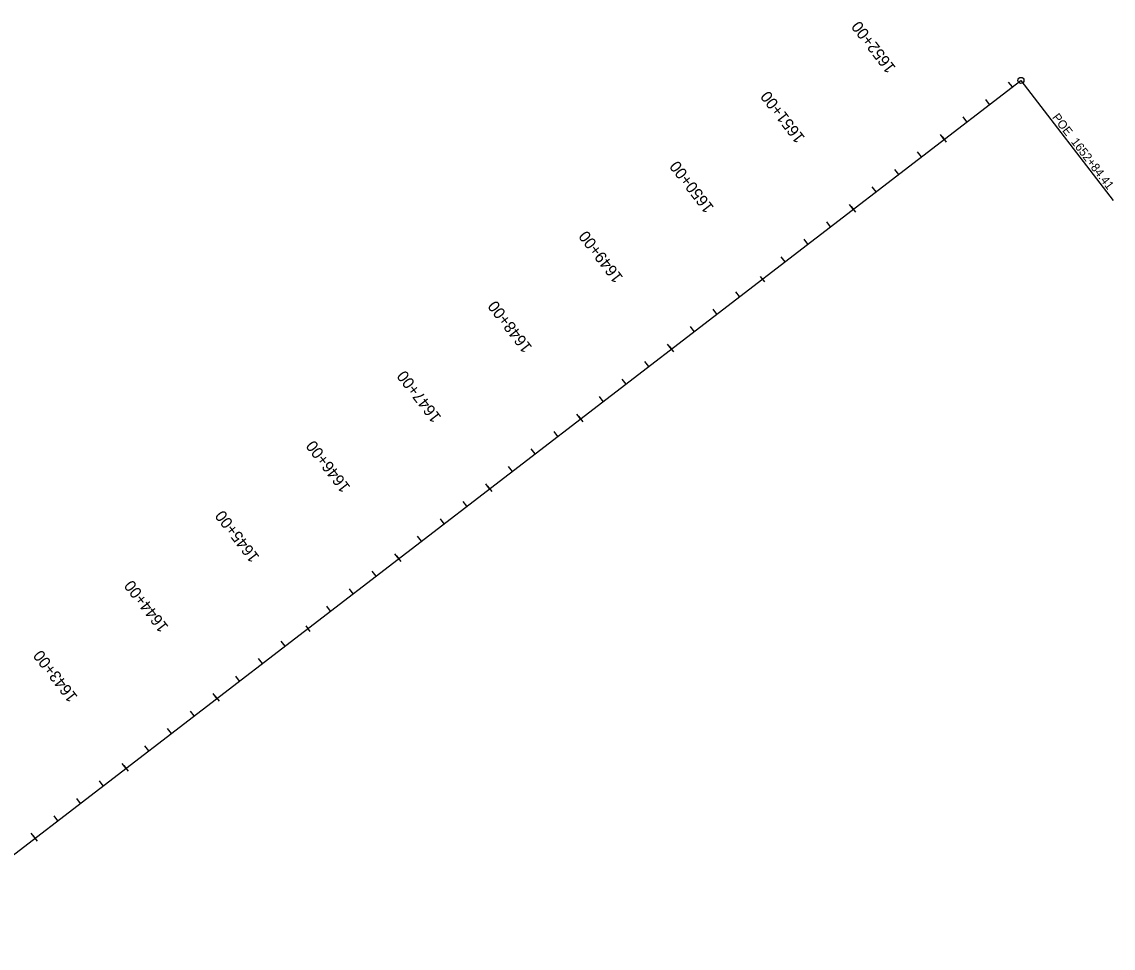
# Model space of a CAD drawing. Extents: x 14119411 to 14122090, y 8669365 to 8673150.
# Drawn here: x 14121138 to 14122090, y 8672343 to 8673150 of the extents above; entities that cross this region are included whole.
import ezdxf

# ---------------------------------------------------------------- set-up
doc = ezdxf.new("R2010")
doc.units = 0
for name, color, linetype in [('Alignment', 7, 'Continuous'), ('Default', 7, 'Continuous'), ('TextAlignment', 7, 'Continuous'), ('TextAlignmentLrg', 7, 'Continuous'), ('TextAlignmentSml', 7, 'Continuous')]:
    doc.layers.add(name, color=color, linetype=linetype)

msp = doc.modelspace()

# ---------------------------------------------------------------- linework, layer by layer
at = {"layer": 'Alignment'}
msp.add_line((14121025.03, 8672342.58), (14122009.4, 8673099.31), dxfattribs=at)
at = {"layer": 'Default'}
msp.add_line((14121025.03, 8672342.58), (14122009.4, 8673099.31), dxfattribs=at)
at = {"layer": 'TextAlignment'}
for p in [(14122009.4, 8673099.31), (14122089.85, 8672994.66)]:
    msp.add_line(p, (14122089.85, 8672994.66), dxfattribs=at)
msp.add_circle((14122009.4, 8673099.31), 2.67, dxfattribs=at)
at = {"layer": 'TextAlignmentLrg'}
for p, q in [((14121942.48, 8673047.87), (14121939.15, 8673052.2)), ((14121863.2, 8672986.92), (14121859.87, 8672991.25)), ((14121782.05, 8672928.4), (14121785.78, 8672923.55)), ((14121704.64, 8672865.03), (14121701.31, 8672869.35)), ((14121625.36, 8672804.08), (14121622.03, 8672808.41)), ((14121546.08, 8672743.13), (14121542.75, 8672747.46)), ((14121466.79, 8672682.19), (14121463.47, 8672686.51)), ((14121385.65, 8672623.66), (14121389.38, 8672618.81)), ((14121308.23, 8672560.29), (14121304.91, 8672564.62)), ((14121228.95, 8672499.34), (14121225.62, 8672503.67)), ((14121149.67, 8672438.4), (14121146.34, 8672442.73))]:
    msp.add_line(p, q, dxfattribs=at)
at = {"layer": 'TextAlignmentSml'}
for p, q in [((14122001.94, 8673093.58), (14121998.61, 8673097.91)), ((14121982.12, 8673078.34), (14121978.79, 8673082.67)), ((14121962.3, 8673063.1), (14121958.97, 8673067.43)), ((14121940.62, 8673050.29), (14121944.35, 8673045.44)), ((14121922.66, 8673032.63), (14121919.33, 8673036.96)), ((14121902.84, 8673017.39), (14121899.51, 8673021.72)), ((14121883.02, 8673002.16), (14121879.69, 8673006.49)), ((14121861.33, 8672989.35), (14121865.06, 8672984.49)), ((14121843.38, 8672971.68), (14121840.05, 8672976.01)), ((14121823.56, 8672956.45), (14121820.23, 8672960.78)), ((14121803.74, 8672941.21), (14121800.41, 8672945.54)), ((14121782.05, 8672928.4), (14121785.78, 8672923.55)), ((14121764.1, 8672910.74), (14121760.77, 8672915.06)), ((14121744.28, 8672895.5), (14121740.95, 8672899.83)), ((14121724.46, 8672880.26), (14121721.13, 8672884.59)), ((14121702.77, 8672867.45), (14121706.5, 8672862.6)), ((14121684.82, 8672849.79), (14121681.49, 8672854.12)), ((14121665, 8672834.55), (14121661.67, 8672838.88)), ((14121645.18, 8672819.32), (14121641.85, 8672823.64)), ((14121623.49, 8672806.5), (14121627.22, 8672801.65)), ((14121605.54, 8672788.84), (14121602.21, 8672793.17)), ((14121585.72, 8672773.61), (14121582.39, 8672777.93)), ((14121565.9, 8672758.37), (14121562.57, 8672762.7)), ((14121544.21, 8672745.56), (14121547.94, 8672740.71)), ((14121526.26, 8672727.9), (14121522.93, 8672732.22)), ((14121506.44, 8672712.66), (14121503.11, 8672716.99)), ((14121486.61, 8672697.42), (14121483.29, 8672701.75)), ((14121464.93, 8672684.61), (14121468.66, 8672679.76)), ((14121446.97, 8672666.95), (14121443.65, 8672671.28)), ((14121427.15, 8672651.71), (14121423.83, 8672656.04)), ((14121407.33, 8672636.47), (14121404.01, 8672640.8)), ((14121385.65, 8672623.66), (14121389.38, 8672618.81)), ((14121367.69, 8672606), (14121364.37, 8672610.33)), ((14121347.87, 8672590.76), (14121344.55, 8672595.09)), ((14121328.05, 8672575.53), (14121324.73, 8672579.86)), ((14121306.37, 8672562.72), (14121310.1, 8672557.87)), ((14121288.41, 8672545.05), (14121285.08, 8672549.38)), ((14121268.59, 8672529.82), (14121265.26, 8672534.15)), ((14121248.77, 8672514.58), (14121245.44, 8672518.91)), ((14121227.09, 8672501.77), (14121230.82, 8672496.92)), ((14121209.13, 8672484.11), (14121205.8, 8672488.44)), ((14121189.31, 8672468.87), (14121185.98, 8672473.2)), ((14121169.49, 8672453.63), (14121166.16, 8672457.96)), ((14121147.81, 8672440.82), (14121151.54, 8672435.97))]:
    msp.add_line(p, q, dxfattribs=at)

# ---------------------------------------------------------------- texts
at = {"layer": 'TextAlignment'}
for s, p in [('POE ', (14122036.31, 8673067.02)), ('1652+84.41', (14122052.7, 8673045.69))]:
    msp.add_text(s, height=7.5, rotation=307.55116, dxfattribs=at).set_placement(p)
at = {"layer": 'TextAlignmentLrg'}
for s, p in [('1650+00', (14121742.18, 8672988.49)), ('1645+00', (14121345.78, 8672683.75))]:
    msp.add_text(s, height=10.02, rotation=127.55116, dxfattribs=at).set_placement(p)
at = {"layer": 'TextAlignmentSml'}
for s, p in [('1652+00', (14121900.74, 8673110.38)), ('1651+00', (14121821.46, 8673049.43)), ('1650+00', (14121742.18, 8672988.49)), ('1649+00', (14121662.9, 8672927.54)), ('1648+00', (14121583.62, 8672866.59)), ('1647+00', (14121504.34, 8672805.65)), ('1646+00', (14121425.06, 8672744.7)), ('1645+00', (14121345.78, 8672683.75)), ('1644+00', (14121266.49, 8672622.81)), ('1643+00', (14121187.21, 8672561.86))]:
    msp.add_text(s, height=10.02, rotation=127.55116, dxfattribs=at).set_placement(p)

doc.saveas('drawing.dxf')
